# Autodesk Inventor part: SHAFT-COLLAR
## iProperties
Created: 2008-03
Part Number: SHAFT-COLLAR
Document SubType Name: Modeling
Density: 1 g/cm^3
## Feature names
1. Extrusion1
2. Hole1
3. Hole2
4. Chamfer1
5. Chamfer2
6. Chamfer3
